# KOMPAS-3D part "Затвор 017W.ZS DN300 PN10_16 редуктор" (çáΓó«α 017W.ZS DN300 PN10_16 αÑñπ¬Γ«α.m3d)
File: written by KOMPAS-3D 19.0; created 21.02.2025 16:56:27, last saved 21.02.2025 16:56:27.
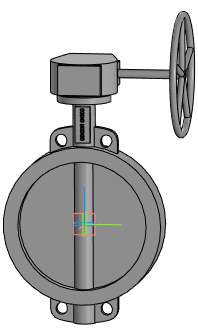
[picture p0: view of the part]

Document properties: Автор: Евгений; Полное имя файла: Затвор 017W.ZS DN300 PN10_16 редуктор.a3d

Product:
- Part/product: Затвор 017W.ZS DN300 PN10_16 редуктор
    Масса: 58.1019

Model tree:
1. Операция без истории:1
